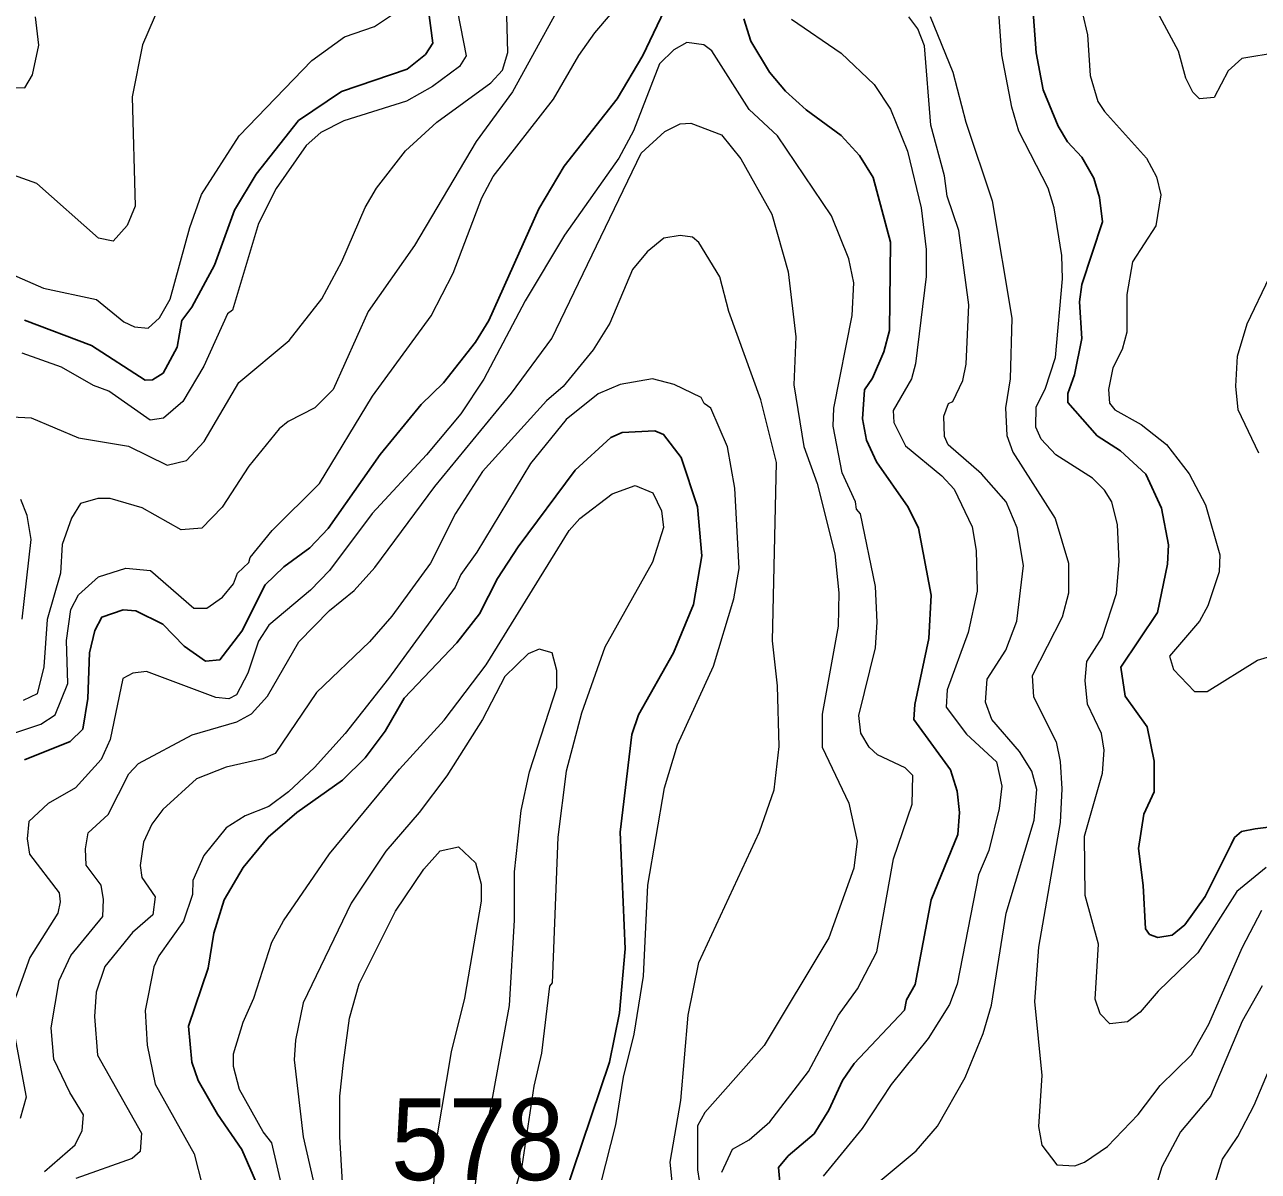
# Model space of a CAD drawing. Extents: x 673.3 to 698.5, y 6984.3 to 7012.3.
# Drawn here: x 681.527 to 682.735, y 6985.361 to 6986.483 of the extents above; entities that cross this region are included whole.
import ezdxf

# ---------------------------------------------------------------- set-up
doc = ezdxf.new("R2010")
doc.units = 0
doc.header["$LTSCALE"] = 0.032
doc.layers.add('1', color=7, linetype='Continuous', lineweight=25)
doc.layers.add('2', color=7, linetype='Continuous', lineweight=13)
doc.layers.add('21', color=7, linetype='Continuous')

msp = doc.modelspace()

# ---------------------------------------------------------------- linework, layer by layer
at = {"layer": '1'}
for points in [[(682.5119, 6986.5263), (682.517, 6986.4556), (682.5237, 6986.4194), (682.5385, 6986.3837), (682.5477, 6986.3683), (682.5616, 6986.3533), (682.5735, 6986.3328), (682.5789, 6986.3139), (682.582, 6986.2901), (682.5616, 6986.2288), (682.5593, 6986.2119), (682.5616, 6986.1759), (682.5544, 6986.1403), (682.5479, 6986.122), (682.5479, 6986.1134), (682.5768, 6986.0808), (682.5997, 6986.066), (682.6242, 6986.0432), (682.6397, 6986.01), (682.6464, 6985.9741), (682.6455, 6985.9552), (682.6357, 6985.9076), (682.6, 6985.8542), (682.604, 6985.8259), (682.6257, 6985.796), (682.6325, 6985.7624), (682.6325, 6985.7323), (682.6224, 6985.7103), (682.6171, 6985.6766), (682.6219, 6985.6407), (682.624, 6985.5981), (682.628, 6985.5926), (682.6362, 6985.5896), (682.6501, 6985.5918), (682.6624, 6985.6022), (682.6825, 6985.6299), (682.708, 6985.6806), (682.7113, 6985.6875), (682.7181, 6985.6935), (682.7314, 6985.696), (682.7551, 6985.699)], [(681.6902, 6986.2065), (681.7124, 6986.2478), (681.732, 6986.3015), (681.7531, 6986.3367), (681.7948, 6986.3893), (681.8367, 6986.4176), (681.9012, 6986.4397), (681.919, 6986.454), (681.9263, 6986.465), (681.9217, 6986.4996)], [(682.1564, 6986.5043), (682.1319, 6986.453), (682.1066, 6986.4106), (682.0547, 6986.3445), (682.0299, 6986.3028), (681.981, 6986.1937), (681.968, 6986.1725), (681.9367, 6986.1326), (681.9148, 6986.1112), (681.8747, 6986.0624), (681.8236, 6985.9899), (681.8057, 6985.9711), (681.7805, 6985.9524)], [(682.2672, 6985.3363), (682.2646, 6985.3646), (682.274, 6985.3758), (682.2996, 6985.3975), (682.3141, 6985.4208), (682.3273, 6985.4497), (682.3389, 6985.4664), (682.388, 6985.5185), (682.39, 6985.5286), (682.3984, 6985.5437), (682.4142, 6985.6266), (682.4403, 6985.6904), (682.4419, 6985.7119), (682.4395, 6985.7328), (682.433, 6985.7539), (682.3973, 6985.8029), (682.3981, 6985.8178), (682.4118, 6985.8823), (682.4142, 6985.9247), (682.4019, 6985.9904), (682.3916, 6986.011), (682.3606, 6986.0551), (682.3508, 6986.0764), (682.3468, 6986.0973), (682.349, 6986.1256), (682.3566, 6986.137), (682.3678, 6986.1628), (682.3735, 6986.1839), (682.3744, 6986.2703), (682.3573, 6986.3335), (682.344, 6986.3552), (682.3261, 6986.3747), (682.2919, 6986.3996), (682.2715, 6986.4179), (682.2559, 6986.4367), (682.2377, 6986.467), (682.2309, 6986.4888)], [(681.5263, 6986.1939), (681.592, 6986.1692), (681.6446, 6986.1353), (681.6517, 6986.1355), (681.6622, 6986.1421), (681.676, 6986.1674), (681.6805, 6986.1934), (681.6902, 6986.2065)], [(681.756, 6985.344), (681.7393, 6985.3823), (681.7155, 6985.4167), (681.6966, 6985.4498), (681.6903, 6985.4676), (681.6871, 6985.5028), (681.7061, 6985.5597), (681.7117, 6985.594), (681.7218, 6985.6266), (681.7405, 6985.6582), (681.765, 6985.6877), (681.7932, 6985.712), (681.8379, 6985.7435), (681.8601, 6985.7656), (681.8794, 6985.7917), (681.898, 6985.824), (681.9496, 6985.878), (681.972, 6985.9066), (681.9897, 6985.941), (682.0097, 6985.9721), (682.0655, 6986.0469), (682.1005, 6986.0791), (682.1117, 6986.0839), (682.1436, 6986.0854), (682.1522, 6986.0819), (682.1694, 6986.0595), (682.1854, 6986.0113), (682.1895, 6985.9633), (682.1814, 6985.9155), (682.162, 6985.8682), (682.1275, 6985.8075), (682.1212, 6985.7884), (682.1098, 6985.6927), (682.1146, 6985.5784), (682.1089, 6985.5158), (682.0992, 6985.4676), (682.0454, 6985.308)], [(681.7805, 6985.9524), (681.762, 6985.9347), (681.7393, 6985.8894), (681.7177, 6985.8615), (681.7037, 6985.8601), (681.6827, 6985.8747), (681.6617, 6985.8964), (681.6354, 6985.9095), (681.6229, 6985.9102), (681.602, 6985.9031), (681.5952, 6985.8902), (681.5902, 6985.8682), (681.5885, 6985.8237), (681.5834, 6985.7937), (681.571, 6985.7815), (681.5264, 6985.7635)]]:
    msp.add_lwpolyline(points, dxfattribs=at)
at = {"layer": '2'}
for points in [[(682.754, 6986.4559), (682.7185, 6986.4499), (682.705, 6986.4378), (682.6914, 6986.4118), (682.6768, 6986.4106), (682.6704, 6986.4169), (682.6635, 6986.4307), (682.6564, 6986.4571), (682.608, 6986.5471)], [(682.0686, 6986.5344), (682.0042, 6986.4174), (681.9687, 6986.3686), (681.9084, 6986.2668), (681.8628, 6986.2024), (681.8288, 6986.1261), (681.8106, 6986.108), (681.7845, 6986.0946), (681.7757, 6986.0876), (681.746, 6986.051), (681.72, 6986.0108), (681.7, 6985.9902), (681.6799, 6985.9885), (681.6417, 6986.0103), (681.6103, 6986.0193), (681.5983, 6986.0194), (681.5814, 6986.0145), (681.5723, 6986.0002)], [(681.4913, 6985.7815), (681.5423, 6985.7985), (681.5565, 6985.8075), (681.5689, 6985.8382), (681.5674, 6985.8804), (681.5718, 6985.9108), (681.5792, 6985.9249), (681.5988, 6985.9427), (681.6257, 6985.951), (681.6497, 6985.9488), (681.6923, 6985.912), (681.7049, 6985.9121), (681.7203, 6985.9226), (681.731, 6985.9358), (681.7351, 6985.9461), (681.7462, 6985.9567), (681.7475, 6985.9617), (681.7688, 6985.988), (681.8152, 6986.034), (681.8673, 6986.1194), (681.9245, 6986.198), (681.9462, 6986.2399), (681.9743, 6986.3136), (681.9854, 6986.3344), (682.0445, 6986.4103), (682.0691, 6986.453), (682.0848, 6986.475), (682.1269, 6986.5246)], [(682.7422, 6985.6582), (682.7136, 6985.6347), (682.6754, 6985.5746), (682.6363, 6985.5371), (682.6189, 6985.5165), (682.6065, 6985.5072), (682.589, 6985.5051), (682.5798, 6985.5151), (682.5747, 6985.5292), (682.5779, 6985.5831), (682.565, 6985.6308), (682.5642, 6985.6888), (682.582, 6985.7505), (682.5836, 6985.773), (682.5809, 6985.7892), (682.5672, 6985.8181), (682.565, 6985.8413), (682.5666, 6985.8598), (682.5815, 6985.8832), (682.5955, 6985.9265), (682.5983, 6985.9581), (682.5967, 6985.9937), (682.5909, 6986.0162), (682.5838, 6986.0274), (682.572, 6986.0392), (682.5361, 6986.0622), (682.5219, 6986.0773), (682.5168, 6986.089), (682.5169, 6986.1089), (682.5258, 6986.1264), (682.5358, 6986.1573), (682.5429, 6986.2342), (682.5421, 6986.2572), (682.5347, 6986.3037), (682.5286, 6986.323), (682.5, 6986.3788), (682.4932, 6986.4022), (682.4835, 6986.4537), (682.4788, 6986.5184)], [(681.6596, 6986.5043), (681.6421, 6986.4635), (681.6317, 6986.4126), (681.6349, 6986.3053), (681.6271, 6986.2866), (681.6132, 6986.2713), (681.5989, 6986.274), (681.5386, 6986.3276), (681.4934, 6986.3436)], [(681.5139, 6986.0992), (681.5331, 6986.0984), (681.5793, 6986.0787), (681.6282, 6986.0705), (681.6662, 6986.0521), (681.6851, 6986.0564), (681.7023, 6986.0752), (681.7363, 6986.1329), (681.7854, 6986.1739), (681.8175, 6986.2148), (681.8372, 6986.2514), (681.8601, 6986.304), (681.8712, 6986.3231), (681.8994, 6986.3596), (681.93, 6986.3876), (681.9829, 6986.4263), (681.9946, 6986.4386), (681.9997, 6986.456), (681.9982, 6986.5039)], [(681.9504, 6986.4961), (681.9589, 6986.4525), (681.9525, 6986.4421), (681.9259, 6986.4227), (681.9003, 6986.4082), (681.8391, 6986.389), (681.8166, 6986.3777), (681.8023, 6986.3649), (681.7727, 6986.3227), (681.7556, 6986.2885), (681.7302, 6986.2037), (681.7253, 6986.2), (681.7019, 6986.1487), (681.6815, 6986.1142), (681.6625, 6986.098), (681.6496, 6986.096), (681.6091, 6986.1243), (681.5941, 6986.1298), (681.5627, 6986.148), (681.524, 6986.1617)], [(681.5044, 6986.4216), (681.5267, 6986.4213), (681.5343, 6986.4341), (681.5403, 6986.463), (681.5372, 6986.4909)], [(681.8078, 6986.448), (681.8399, 6986.4713), (681.8692, 6986.4814), (681.8867, 6986.4929)], [(682.2774, 6986.4886), (682.3261, 6986.4553)], [(682.3622, 6985.3497), (682.3994, 6985.3808), (682.4203, 6985.4049), (682.4475, 6985.4525), (682.4652, 6985.4957), (682.4731, 6985.5233), (682.4875, 6985.6136), (682.5151, 6985.7045), (682.5176, 6985.7344), (682.5128, 6985.7524), (682.5007, 6985.7717), (682.4736, 6985.8031), (682.4673, 6985.8201), (682.4689, 6985.8426), (682.4874, 6985.871), (682.4982, 6985.8992), (682.5046, 6985.9537), (682.4985, 6985.9907), (682.4875, 6986.0162), (682.4636, 6986.0434), (682.4308, 6986.072), (682.4273, 6986.0801), (682.4266, 6986.0998), (682.431, 6986.1124), (682.4355, 6986.1142), (682.4451, 6986.1349), (682.4483, 6986.1509), (682.4509, 6986.209), (682.4411, 6986.2817), (682.4299, 6986.3153), (682.4273, 6986.3352), (682.4139, 6986.3847), (682.4077, 6986.4624), (682.4011, 6986.479), (682.3922, 6986.4909)], [(682.4133, 6986.4912), (682.4353, 6986.4367), (682.4481, 6986.3876), (682.4738, 6986.3108), (682.4932, 6986.1959), (682.4916, 6986.1365), (682.4868, 6986.108), (682.4884, 6986.0811), (682.4942, 6986.0648), (682.5357, 6985.9997), (682.5486, 6985.9559), (682.5486, 6985.9267), (682.5424, 6985.9031), (682.5129, 6985.8457), (682.5145, 6985.8251), (682.5366, 6985.781), (682.5405, 6985.7619), (682.5421, 6985.735), (682.5405, 6985.7021), (682.5194, 6985.5803), (682.5153, 6985.5269), (682.5225, 6985.4545), (682.5194, 6985.4048), (682.5224, 6985.3864), (682.5373, 6985.3672), (682.5548, 6985.3663), (682.5644, 6985.3697), (682.5869, 6985.3852), (682.6167, 6985.4165), (682.6384, 6985.4447), (682.669, 6985.4748), (682.6862, 6985.5047), (682.7187, 6985.5795), (682.7378, 6985.6164)], [(682.5622, 6986.494), (682.5674, 6986.4732), (682.5698, 6986.4334), (682.5775, 6986.408), (682.5838, 6986.398), (682.6251, 6986.3525), (682.6348, 6986.3341), (682.6389, 6986.3165), (682.634, 6986.2863), (682.6112, 6986.2509), (682.6057, 6986.2191), (682.6056, 6986.1821), (682.6012, 6986.1651), (682.5919, 6986.1473), (682.5877, 6986.1259), (682.5889, 6986.1126), (682.5939, 6986.1062), (682.6198, 6986.0918), (682.6447, 6986.0723), (682.6669, 6986.0436), (682.6829, 6986.0132), (682.6967, 6985.9643), (682.696, 6985.9475), (682.685, 6985.9143), (682.6768, 6985.8994), (682.6474, 6985.865), (682.6513, 6985.852), (682.672, 6985.8305), (682.6844, 6985.8305), (682.7338, 6985.8611), (682.7435, 6985.864)], [(682.3386, 6986.2304), (682.3337, 6986.2538), (682.3167, 6986.2961), (682.2638, 6986.3743), (682.2358, 6986.4), (682.1994, 6986.4574), (682.1916, 6986.4632), (682.1749, 6986.4657), (682.1621, 6986.4585), (682.1481, 6986.4449), (682.1226, 6986.3793), (682.1083, 6986.3523), (682.0553, 6986.277), (682.0165, 6986.2127), (681.9762, 6986.1361), (681.9536, 6986.1023), (681.9201, 6986.0621), (681.8667, 6986.0047), (681.825, 6985.9489), (681.8065, 6985.9296), (681.7657, 6985.8952), (681.7556, 6985.8797), (681.745, 6985.8485), (681.7339, 6985.827), (681.7265, 6985.8232), (681.7136, 6985.8246), (681.6458, 6985.8499), (681.6326, 6985.8485), (681.6227, 6985.8433), (681.6104, 6985.7833), (681.6015, 6985.7638), (681.5763, 6985.736), (681.5497, 6985.7207), (681.5307, 6985.7033), (681.529, 6985.6862), (681.5314, 6985.6711), (681.5605, 6985.6335), (681.5615, 6985.6247), (681.559, 6985.6136), (681.5316, 6985.5702), (681.5161, 6985.5262)], [(681.4582, 6986.2629), (681.5451, 6986.2253), (681.5969, 6986.2142), (681.6238, 6986.1924), (681.6341, 6986.1872), (681.6474, 6986.1862), (681.6585, 6986.1961), (681.6692, 6986.2143), (681.6883, 6986.2846), (681.6998, 6986.3169), (681.7366, 6986.3743), (681.8078, 6986.448)], [(682.3261, 6986.4553), (682.3585, 6986.4246), (682.3745, 6986.4004), (682.3911, 6986.3593), (682.4045, 6986.3039), (682.4092, 6986.2631), (682.4093, 6986.2366), (682.3987, 6986.1512), (682.3949, 6986.1366), (682.3769, 6986.1053), (682.3777, 6986.0938), (682.3889, 6986.0709), (682.4246, 6986.0416), (682.4368, 6986.0286), (682.4542, 6985.9915), (682.4583, 6985.9683), (682.4591, 6985.9285), (682.4503, 6985.8881), (682.4298, 6985.8321), (682.429, 6985.8151), (682.4489, 6985.7887), (682.4781, 6985.7617), (682.4834, 6985.7379), (682.4809, 6985.7159), (682.4706, 6985.6747), (682.4606, 6985.6511), (682.4396, 6985.5441), (682.432, 6985.5241), (682.4111, 6985.4907), (682.375, 6985.4459), (682.3467, 6985.4028), (682.3084, 6985.3562)], [(681.5461, 6985.3606), (681.576, 6985.3866), (681.5828, 6985.4008), (681.5843, 6985.4161), (681.5707, 6985.4378), (681.5551, 6985.4706), (681.5526, 6985.5011), (681.5602, 6985.5477), (681.5717, 6985.5721), (681.6031, 6985.6101), (681.6039, 6985.6269), (681.6016, 6985.641), (681.5867, 6985.6604), (681.5861, 6985.6764), (681.5889, 6985.6922), (681.6082, 6985.7102), (681.6286, 6985.7497), (681.638, 6985.7601), (681.6906, 6985.7879), (681.7343, 6985.8007), (681.7488, 6985.8085), (681.7643, 6985.8257), (681.7949, 6985.879), (681.825, 6985.9098), (681.8493, 6985.9292), (681.8693, 6985.9518), (681.9282, 6986.031), (682.0034, 6986.1223), (682.0429, 6986.1759), (682.1301, 6986.3573), (682.1534, 6986.3784), (682.1684, 6986.3859), (682.1787, 6986.3868), (682.2088, 6986.3754), (682.2277, 6986.3517), (682.258, 6986.2977), (682.2742, 6986.2412), (682.2815, 6986.1777), (682.2798, 6986.1306), (682.2896, 6986.0702), (682.3027, 6986.0339), (682.3199, 6985.9651), (682.3238, 6985.9269), (682.3231, 6985.8943), (682.3076, 6985.8083), (682.3074, 6985.7761), (682.3337, 6985.7212), (682.3418, 6985.684), (682.3385, 6985.6576), (682.3139, 6985.5892), (682.2507, 6985.4839), (682.1927, 6985.4185), (682.1855, 6985.4054), (682.1855, 6985.3621), (682.1903, 6985.3308)], [(682.1643, 6985.3151), (682.1586, 6985.3698), (682.1692, 6985.4301), (682.1763, 6985.5135), (682.1868, 6985.5653), (682.246, 6985.693), (682.2603, 6985.7342), (682.2652, 6985.7765), (682.2636, 6985.836), (682.2588, 6985.88), (682.2628, 6986.0544), (682.2473, 6986.1158), (682.2162, 6986.2024), (682.2073, 6986.2363), (682.1866, 6986.2698), (682.1806, 6986.275), (682.1683, 6986.2767), (682.1524, 6986.274), (682.136, 6986.2606), (682.1218, 6986.2435), (682.0994, 6986.191), (682.0832, 6986.1649), (682.054, 6986.129), (682.0374, 6986.1148), (681.9749, 6986.0458), (681.9483, 6986.0046), (681.924, 6985.956), (681.8861, 6985.9043), (681.8643, 6985.8792), (681.8124, 6985.8296), (681.7718, 6985.7697), (681.7599, 6985.7644), (681.724, 6985.7564), (681.6947, 6985.745), (681.6618, 6985.7148), (681.651, 6985.7005), (681.6428, 6985.683), (681.6397, 6985.6601), (681.6414, 6985.6484), (681.6544, 6985.6293), (681.652, 6985.6117), (681.6322, 6985.5947), (681.6052, 6985.5612), (681.5967, 6985.536), (681.5951, 6985.5123), (681.5978, 6985.4745), (681.6409, 6985.3983), (681.6397, 6985.3803), (681.6319, 6985.3734), (681.5766, 6985.3537)], [(682.2091, 6985.3601), (682.2198, 6985.3826), (682.2359, 6985.3915), (682.2561, 6985.4092), (682.2941, 6985.4586), (682.3235, 6985.5136), (682.3421, 6985.5395), (682.3609, 6985.5755), (682.3774, 6985.6666), (682.3956, 6985.72), (682.3961, 6985.7483), (682.3888, 6985.7558), (682.3617, 6985.7685), (682.3534, 6985.7759), (682.3452, 6985.7896), (682.3435, 6985.8069), (682.3598, 6985.8731), (682.3614, 6985.8982), (682.3597, 6985.9331), (682.3451, 6986.0042), (682.341, 6986.0089), (682.3401, 6986.0162), (682.327, 6986.0445), (682.3182, 6986.0902), (682.319, 6986.1077), (682.3369, 6986.1984), (682.3386, 6986.2304)], [(682.735, 6986.0637), (682.7147, 6986.106), (682.7124, 6986.1293), (682.714, 6986.1585), (682.7237, 6986.1902), (682.7456, 6986.2358)], [(682.0763, 6985.292), (682.1055, 6985.4064), (682.113, 6985.4529), (682.1235, 6985.495), (682.1325, 6985.5518), (682.1368, 6985.6409), (682.1529, 6985.7363), (682.1657, 6985.7782), (682.2009, 6985.8552), (682.2211, 6985.9211), (682.2261, 6985.9508), (682.222, 6986.0295), (682.2147, 6986.0699), (682.1985, 6986.1079), (682.192, 6986.1123), (682.189, 6986.1182), (682.1625, 6986.1308), (682.1412, 6986.1366), (682.1097, 6986.131), (682.088, 6986.1217), (682.0569, 6986.0968), (682.0217, 6986.0536), (681.9693, 6985.9667), (681.9535, 6985.9448), (681.948, 6985.9326), (681.8828, 6985.843), (681.8405, 6985.7893), (681.8105, 6985.756), (681.785, 6985.7321), (681.7658, 6985.718), (681.7426, 6985.7088), (681.7238, 6985.697), (681.702, 6985.6698), (681.6911, 6985.6453), (681.6909, 6985.6316), (681.6821, 6985.6057), (681.6579, 6985.5718), (681.6532, 6985.561), (681.6447, 6985.5181), (681.6466, 6985.4842), (681.6542, 6985.4462), (681.6926, 6985.378), (681.7007, 6985.346)], [(681.7863, 6985.3125), (681.7685, 6985.3888), (681.7601, 6985.3995), (681.7369, 6985.441), (681.7311, 6985.4635), (681.7311, 6985.4757), (681.7404, 6985.5069), (681.7511, 6985.5302), (681.7687, 6985.5851), (681.78, 6985.606), (681.825, 6985.6715), (681.8936, 6985.7545), (681.9374, 6985.8023), (681.9785, 6985.8565), (682.0596, 6985.988), (682.0703, 6985.9997), (682.1018, 6986.0239), (682.1245, 6986.0322), (682.1415, 6986.0248), (682.1501, 6986.0074), (682.152, 6985.991), (682.1412, 6985.9571), (682.0946, 6985.8737), (682.0719, 6985.8093), (682.0568, 6985.7526), (682.0487, 6985.6878), (682.043, 6985.5452), (682.0405, 6985.542), (682.0325, 6985.4765), (682.025, 6985.4443), (682.0134, 6985.3657), (682.0078, 6985.3465)], [(681.5242, 6985.9011), (681.5331, 6985.9793), (681.5291, 6986.0028), (681.5229, 6986.0185)], [(681.5723, 6986.0002), (681.5633, 6985.9743), (681.5616, 6985.9461), (681.5486, 6985.9008), (681.5453, 6985.8547), (681.5387, 6985.8281), (681.525, 6985.8216)], [(681.9607, 6985.2884), (681.9705, 6985.3701), (681.9826, 6985.4215), (682.0014, 6985.523), (682.0062, 6985.6067), (682.0063, 6985.654), (682.0128, 6985.7138), (682.0208, 6985.7517), (682.0478, 6985.8343), (682.0478, 6985.8511), (682.0431, 6985.8682), (682.0305, 6985.8719), (682.0196, 6985.8672), (681.9966, 6985.845), (681.9747, 6985.8031), (681.9398, 6985.748), (681.913, 6985.7121), (681.8802, 6985.6743), (681.8462, 6985.6234), (681.7994, 6985.5257), (681.7916, 6985.4893), (681.7906, 6985.4698), (681.7992, 6985.3947), (681.8091, 6985.3519)], [(681.8377, 6985.3498), (681.8351, 6985.3946), (681.8351, 6985.4343), (681.8388, 6985.4672), (681.8446, 6985.5108), (681.8542, 6985.5444), (681.8898, 6985.6155), (681.9173, 6985.6564), (681.9333, 6985.6744), (681.9513, 6985.6783), (681.9681, 6985.6628), (681.9736, 6985.6419), (681.9736, 6985.6251), (681.9572, 6985.5303), (681.9441, 6985.4777), (681.9298, 6985.3927), (681.9166, 6985.1886)], [(682.7383, 6985.5422), (682.7187, 6985.5078), (682.6877, 6985.4345), (682.6584, 6985.3995), (682.6401, 6985.3653), (682.6236, 6985.3109)], [(682.6801, 6985.3103), (682.6994, 6985.3728), (682.7144, 6985.395), (682.7305, 6985.4255), (682.7657, 6985.5091)], [(681.5161, 6985.4976), (681.5282, 6985.4334), (681.5223, 6985.4125)]]:
    msp.add_lwpolyline(points, dxfattribs=at)

# ---------------------------------------------------------------- texts
at = {"layer": '21', "width": 0.95}
msp.add_text('578', height=0.08, dxfattribs=at).set_placement((681.8853, 6985.3522))

doc.saveas('drawing.dxf')
